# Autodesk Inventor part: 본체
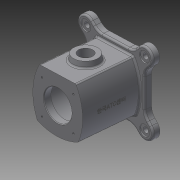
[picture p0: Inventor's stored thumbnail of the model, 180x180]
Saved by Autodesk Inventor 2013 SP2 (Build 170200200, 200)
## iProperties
Created: 2022-01
Part Number: 본체
Material: Generic
Document SubType Name: Modeling
Designer: i
Density: 1 g/cm^3
Author: i
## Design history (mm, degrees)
sketch "스케치1"
  geometry: L1 (-45, -45)-(45, -45); L2 (45, -45)-(45, 45); L3 (45, 45)-(-45, 45); L4 (-45, 45)-(-45, -45); L5 (-45, -45)-(45, 45); L6 (45, -45)-(-45, 45); 1 further point
  constraints: 12 end point, 2 midpoint, 2 parallel, 1 horizontal, 1 perpendicular
  dimensions: "d0" = 90 distance of L3.end L2.end; "d1" = 90 distance of L2.end L1.end
extrude "돌출1" new body sketch "스케치1" distance "d3" = 98; taper "d4" = 0 deg
sketch "스케치2"
  geometry: L1 (-45, -45)-(45, -45) reference; L2 (45, -45)-(45, 45) reference; L3 (-45, 45)-(-45, -45) reference; L4 (-45, -45)-(-45, 45) reference; L5 (-45, 45)-(45, 45) reference; L6 (45, 45)-(45, -45) reference; L7 (45, -45)-(-45, -45) reference; A1 r 90 centre (45, 0) between (-32.942, 45) and (-32.942, -45); A2 r 90 centre (-45, 0) between (32.942, -45) and (32.942, 45); A3 r 90 centre (0, 45) between (-45, -32.942) and (45, -32.942); 4 further points
  constraints: 9 point on circle, 6 point on line, 3 centre point, 3 midpoint
  dimensions: "d5" = 90 radius of A1; "d6" = 90 radius of A2; "d7" = 90 radius of A3
extrude "돌출2" cut sketch "스케치2" stored distance "d8" = 10; taper "d9" = 0 deg
sketch "스케치3"
  geometry: L1 (0, 98)-(0, 0); L2 (-45, 0)-(-45, 98) reference; L3 (-45, 98)-(45, 98) reference; L4 (45, 98)-(45, 0) reference; L5 (45, 0)-(-45, 0) reference; L6 (25, 98)-(25, 86); L7 (25, 86)-(37, 86); L8 (37, 86)-(37, 0); L9 (37, 0)-(0, 0); L10 (25, 98)-(0, 98)
  constraints: 12 end point, 4 perpendicular, 2 point on line, 1 parallel, 1 vertical
  dimensions: "d13" = 50 diameter of L6 L1; "d15" = 12 distance of L6.start L6.end; "d16" = 74 diameter of L8 L1
revolve "회전1" sketch "스케치3" stored, may be unused: angle "d17" = 90 deg
node "작업 평면1"
sketch "스케치4"
  geometry: L1 (-53, -53)-(53, -53); L2 (53, -53)-(53, 53); L3 (53, 53)-(-53, 53); L4 (-53, 53)-(-53, -53); L5 (-53, -53)-(53, 53); L6 (53, -53)-(-53, 53); 1 further point
  constraints: 12 end point, 2 midpoint, 2 parallel, 1 horizontal, 1 perpendicular
  dimensions: "d19" = 106 distance of L3.end L2.end; "d20" = 106 distance of L2.end L1.end
extrude "돌출3" join sketch "스케치4" distance "d21" = 12; taper "d22" = 0 deg
sketch "스케치5"
  geometry: C1 r 25 at (0, 0); 1 further point
  constraints: 1 centre point, 1 coincident
  dimensions: "d23" = 50 diameter of C1
extrude "돌출4" cut sketch "스케치5" distance "d24" = 12; taper "d25" = 0 deg
fillet "모깎기1" dims "d26" = 3
fillet "모깎기2" dims "d27" = 3
sketch "스케치6"
  geometry: L1 (-53, 53)-(53, 53) reference; L2 (53, 53)-(53, -53) reference; L3 (53, -53)-(-53, -53) reference; L4 (-53, -53)-(-53, 53) reference; L5 (-53, 53)-(53, 53) reference; L6 (-53, 31.787)-(-63.607, 42.393); L7 (-31.787, 53)-(-42.393, 63.607); C1 r 25 at (0, 0) reference; A1 r 15 centre (-53, 53) between (-63.607, 42.393) and (-42.393, 63.607)
  constraints: 4 end point, 2 point on circle, 2 point on line, 2 tangent, 1 centre point, 1 coincident, 1 parallel
  dimensions: "d32" = 30 diameter of A1; "d33" = 45 deg angle of L7 L1
extrude "돌출5" join sketch "스케치6" distance "d34" = 12; taper "d35" = 0 deg
sketch "스케치8"
  geometry: C1 r 9 at (53, 53); A1 r 15 centre (53, 53) between (63.607, 42.393) and (42.393, 63.607) reference; 1 further point
  constraints: 1 centre point, 1 coincident
  dimensions: "d36" = 18 diameter of C1
extrude "돌출6" cut sketch "스케치8" distance "d37" = 2; taper "d38" = 0 deg
sketch "스케치9"
  geometry: C1 r 9 at (0, 0) reference; C2 r 4.5 at (0, 0); 1 further point
  constraints: 1 centre point, 1 coincident
  dimensions: "d39" = 9 diameter of C2
extrude "돌출7" cut sketch "스케치9" stored distance "d40" = 2; taper "d41" = 0 deg
node "작업 평면2"
sketch "스케치10"
  geometry: L1 (-31.787, -12)-(31.787, -12) reference; L2 (0, -12)-(0, 49); C1 r 20 at (1.415, 49); 1 further point
  constraints: 2 end point, 1 centre point, 1 midpoint, 1 perpendicular
  dimensions: "d46" = 61 distance of L2.start L2.end; "d47" = 40 diameter of C1
extrude "돌출8" join sketch "스케치10" stored distance "d48" = 2; taper "d49" = 10 deg
sketch "스케치11"
  geometry: C1 r 20 at (0, 0) reference; C2 r 12 at (0, 0); 1 further point
  constraints: 1 centre point, 1 coincident
  dimensions: "d50" = 24 diameter of C2
extrude "돌출9" cut sketch "스케치11" distance "d51" = 13; taper "d52" = 0 deg
sketch "스케치12"
  geometry: L1 (-53, -12)-(-53, 0) reference; L2 (-53, 0)-(-45, 0) reference; L3 (-45, 0)-(-45, 98) reference; L4 (-45, 98)-(-25, 98) reference; L5 (-25, 98)-(-25, 86) reference; L6 (-25, 86)-(-34, 86) reference; L7 (-37, 83)-(-37, 3) reference; L8 (-34, 0)-(-25, 0) reference; L9 (-25, 0)-(-25, -12) reference; L10 (-25, -12)-(-53, -12) reference; L11 (45, 0)-(53, 0) reference; L12 (53, 0)-(53, -12) reference; L13 (53, -12)-(25, -12) reference; L14 (25, -12)-(25, 0) reference; L15 (25, 0)-(34, 0) reference; L16 (37, 3)-(37, 83) reference; L17 (34, 86)-(25, 86) reference; L18 (25, 86)-(25, 98) reference; L19 (25, 98)-(45, 98) reference; L20 (45, 98)-(45, 0) reference; L21 (25, -12)-(-25, -12) reference; L22 (0, -12)-(0, 49); C1 r 15 at (0, 49); A1 r 3 centre (-34, 83) between (-34, 86) and (-37, 83) reference; A2 r 3 centre (-34, 3) between (-37, 3) and (-34, 0) reference; A3 r 3 centre (34, 3) between (34, 0) and (37, 3) reference; A4 r 3 centre (34, 83) between (37, 83) and (34, 86) reference; 1 further point
  constraints: 2 end point, 1 centre point, 1 coincident, 1 midpoint, 1 perpendicular
  dimensions: "d54" = 61 distance of L22.start L22.end; "d55" = 30 diameter of C1
extrude "돌출10" cut sketch "스케치12" distance "d56" = 42; taper "d57" = 0 deg
chamfer "모따기1" distance "d58" = 1; stored, may be unused: second distance "d59" = 2, angle "d60" = 45 deg
chamfer "모따기2" distance "d61" = 1; stored, may be unused: second distance "d62" = 2, angle "d63" = 45 deg
sketch "스케치13"
  geometry: L1 (0, 0)-(28.284, 28.284); L2 (-31.787, -53)-(31.787, -53) reference; C1 r 26 at (0, 0) reference; 1 further point
  constraints: 2 end point, 1 coincident
  dimensions: "d64" = 40 distance of L1.start L1.end; "d65" = 45 deg angle of L2 L1
hole "구멍1" sketch "스케치13" at (28.284, 28.284) diameter "d66" = 3.242; stored, may be unused: countersink angle "d70" = 90 deg, drill point angle "d72" = 118 deg; dims "d67" = 9, "d68" = 4, "d69" = 2, "d71" = 11
sketch "스케치15"
  geometry: L1 (-42.393, -63.607)-(-31.787, -53) reference; L2 (0, 0)-(28.284, 28.284); C1 r 26 at (0, 0) reference; 1 further point
  constraints: 2 end point, 1 coincident, 1 parallel
  dimensions: "d76" = 40 distance of L2.start L2.end
hole "구멍2" sketch "스케치15" at (28.284, 28.284) diameter "d77" = 3.242; stored, may be unused: countersink angle "d81" = 90 deg, drill point angle "d83" = 118 deg; dims "d78" = 9, "d79" = 4, "d80" = 2, "d82" = 11
fillet "모깎기3" dims "d87" = 20
fillet "모깎기4" dims "d88" = 3
fillet "모깎기5" dims "d89" = 3
fillet "모깎기6" dims "d90" = 3
fillet "모깎기7" dims "d91" = 3
node "작업 평면4"
sketch "스케치16"
  geometry: L1 (-23.503, -12)-(23.503, -12) reference; L2 (55, 69)-(55, 29) reference; 2 further points
  constraints: 1 other
feature "엠보싱1" sketch "스케치16" dims "d0" = 90, "d1" = 90, "d7" = 90, "d95" = 0.5, "d96" = 0
node "솔리드1"
pattern_circular "원형 패턴1" dims "d43" = 360 deg
pattern_circular "원형 패턴2" dims angle "d74" = 360 deg
pattern_circular "원형 패턴3" dims angle "d85" = 360 deg
node "절단 모서리 투영1"
node "절단 모서리 투영2"
node "절단 모서리 투영3"
node "절단 모서리 투영4"
other parameters: "d18" = -12, "d45" = 55
